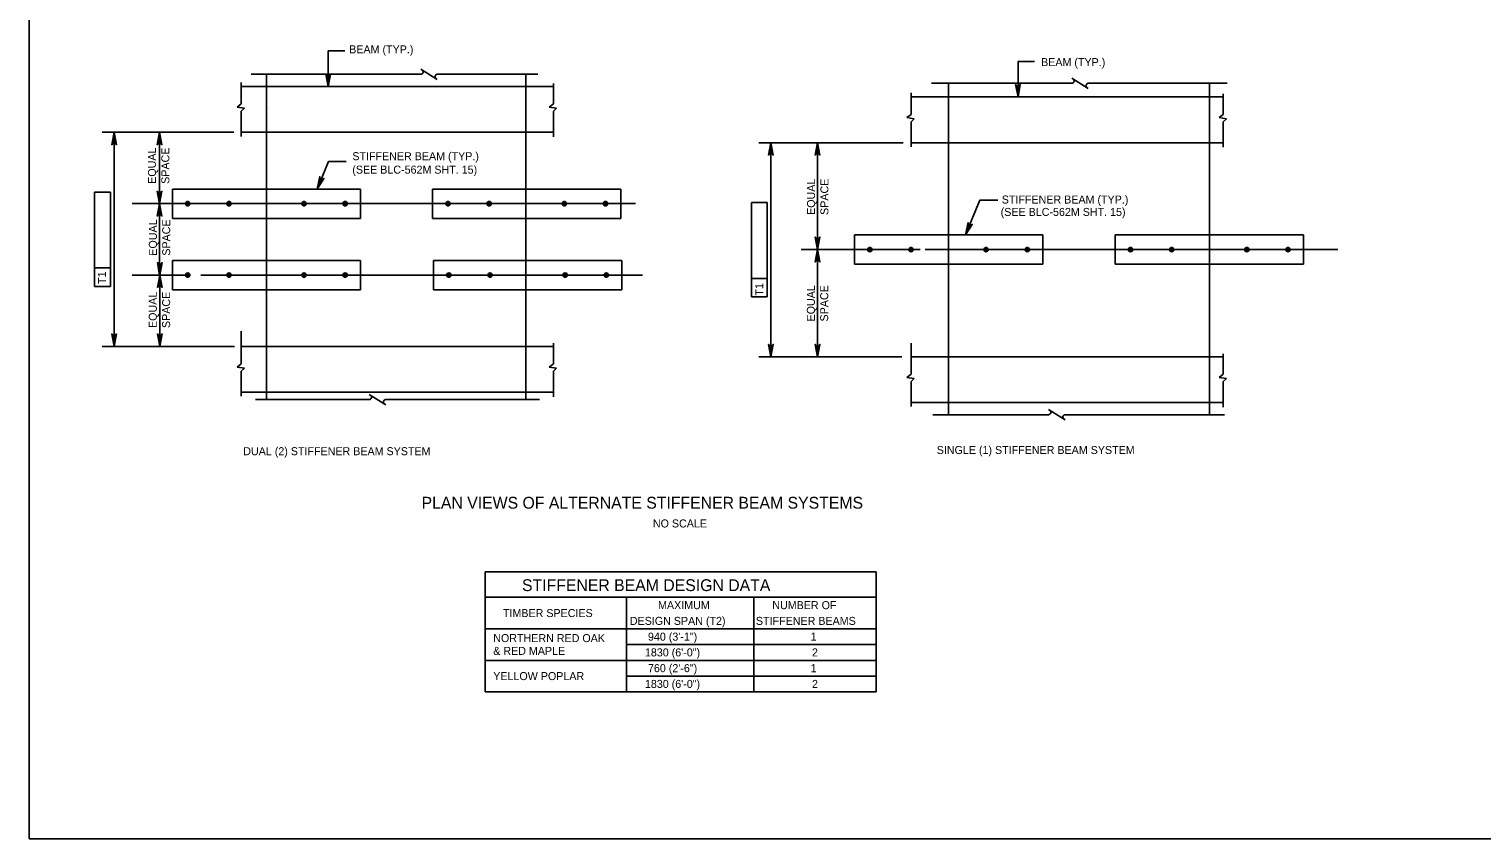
# Model space of a CAD drawing. Extents: x 638263 to 640360, y 293683 to 298655.
# Drawn here: x 639316 to 639861, y 295480 to 295784 of the extents above; entities that cross this region are included whole.
import ezdxf

# ---------------------------------------------------------------- set-up
doc = ezdxf.new("R2010")
doc.units = 0
for name, color, linetype in [('10', 7, 'Continuous'), ('2', 7, 'Continuous'), ('3', 7, 'Continuous'), ('4', 7, 'Continuous'), ('8', 7, 'Continuous')]:
    doc.layers.add(name, color=color, linetype=linetype)

msp = doc.modelspace()

# ---------------------------------------------------------------- linework, layer by layer
at = {"layer": '10'}
for p, q in [((639487.48, 295580.54), (639487.48, 295535.57)), ((639487.48, 295580.54), (639634.13, 295580.54)), ((639634.13, 295580.54), (639634.13, 295535.57)), ((639487.48, 295571), (639634.13, 295571)), ((639540.46, 295571), (639540.46, 295535.57)), ((639588.23, 295571), (639588.23, 295535.57)), ((639487.48, 295559.19), (639634.13, 295559.19)), ((639540.46, 295553.28), (639634.13, 295553.28)), ((639487.48, 295547.38), (639634.13, 295547.38)), ((639540.46, 295541.47), (639634.13, 295541.47)), ((639487.48, 295535.57), (639634.13, 295535.57))]:
    msp.add_line(p, q, dxfattribs=at)
at = {"layer": '2'}
for p, q in [((639316.46, 295480.46), (639316.46, 296044.46)), ((639405.49, 295645.1), (639405.49, 295767.05)), ((639502.74, 295645.1), (639502.74, 295767.05)), ((639661.25, 295639.44), (639661.25, 295763.63)), ((639759.08, 295639.44), (639759.08, 295763.63)), ((640102.46, 295480.46), (639316.46, 295480.46))]:
    msp.add_line(p, q, dxfattribs=at)
at = {"layer": '3'}
for p, q in [((639399.75, 295767.05), (639463.3, 295767.05)), ((639463.37, 295768.98), (639469.53, 295765.11)), ((639469.51, 295767.05), (639507.21, 295767.05)), ((639707.48, 295765.57), (639713.64, 295761.7)), ((639395.99, 295755.88), (639395.99, 295763.98)), ((639395.99, 295762.42), (639513.06, 295762.42)), ((639513.06, 295755.88), (639513.06, 295763.61)), ((639647.19, 295751.96), (639647.19, 295760.06)), ((639654.87, 295763.63), (639707.41, 295763.63)), ((639713.63, 295763.63), (639765.7, 295763.63)), ((639394.45, 295754.69), (639395.99, 295755.88)), ((639397.21, 295754.27), (639394.45, 295754.69)), ((639511.52, 295754.69), (639513.06, 295755.88)), ((639514.28, 295754.27), (639511.52, 295754.69)), ((639647.19, 295758.5), (639764.26, 295758.5)), ((639764.26, 295751.96), (639764.26, 295759.68)), ((639395.99, 295753.17), (639397.21, 295754.27)), ((639395.99, 295743.75), (639395.99, 295753.17)), ((639513.06, 295753.17), (639514.28, 295754.27)), ((639513.06, 295743.56), (639513.06, 295753.17)), ((639645.65, 295750.77), (639647.19, 295751.96)), ((639648.4, 295750.34), (639645.65, 295750.77)), ((639647.19, 295749.25), (639648.4, 295750.34)), ((639647.19, 295739.83), (639647.19, 295749.25)), ((639762.72, 295750.77), (639764.26, 295751.96)), ((639765.48, 295750.34), (639762.72, 295750.77)), ((639764.26, 295749.25), (639765.48, 295750.34)), ((639764.26, 295739.64), (639764.26, 295749.25)), ((639513.06, 295745.29), (639395.99, 295745.29)), ((639764.26, 295741.37), (639647.19, 295741.37)), ((639370.2, 295724.02), (639370.2, 295713)), ((639370.2, 295724.02), (639440.77, 295724.02)), ((639440.77, 295724.02), (639440.77, 295713)), ((639467.79, 295724.02), (639467.79, 295713)), ((639467.79, 295724.02), (639538.36, 295724.02)), ((639538.36, 295724.02), (639538.36, 295713)), ((639405.4, 295718.54), (639405.4, 295718.54)), ((639370.2, 295713), (639440.77, 295713)), ((639467.79, 295713), (639538.36, 295713)), ((639625.96, 295706.82), (639696.54, 295706.82)), ((639625.96, 295706.82), (639625.96, 295695.8)), ((639696.54, 295706.82), (639696.54, 295695.8)), ((639723.71, 295706.82), (639723.71, 295695.8)), ((639723.71, 295706.82), (639794.28, 295706.82)), ((639794.28, 295706.82), (639794.28, 295695.8)), ((639370.2, 295697.27), (639440.77, 295697.27)), ((639370.2, 295697.27), (639370.2, 295686.25)), ((639440.77, 295697.27), (639440.77, 295686.25)), ((639468.12, 295697.27), (639538.69, 295697.27)), ((639468.12, 295697.27), (639468.12, 295686.25)), ((639538.69, 295697.27), (639538.69, 295686.25)), ((639625.96, 295695.8), (639696.54, 295695.8)), ((639723.71, 295695.8), (639794.28, 295695.8)), ((639405.4, 295691.79), (639405.4, 295691.79)), ((639370.2, 295686.25), (639440.77, 295686.25)), ((639468.12, 295686.25), (639538.69, 295686.25)), ((639395.99, 295658.5), (639395.99, 295670.77)), ((639395.99, 295658.5), (639395.99, 295666.6)), ((639395.99, 295665.04), (639513.06, 295665.04)), ((639513.06, 295658.5), (639513.06, 295666.22)), ((639647.19, 295658.24), (639647.19, 295666.19)), ((639647.19, 295654.58), (639647.19, 295662.68)), ((639764.26, 295654.58), (639764.26, 295662.3)), ((639394.45, 295657.31), (639395.99, 295658.5)), ((639397.21, 295656.89), (639394.45, 295657.31)), ((639395.99, 295655.79), (639397.21, 295656.89)), ((639511.52, 295657.31), (639513.06, 295658.5)), ((639514.28, 295656.89), (639511.52, 295657.31)), ((639513.06, 295655.79), (639514.28, 295656.89)), ((639647.19, 295661.12), (639764.26, 295661.12)), ((639395.99, 295646.37), (639395.99, 295655.79)), ((639513.06, 295646.18), (639513.06, 295655.79)), ((639645.65, 295653.39), (639647.19, 295654.58)), ((639648.41, 295652.97), (639645.65, 295653.39)), ((639647.19, 295651.87), (639648.41, 295652.97)), ((639647.19, 295642.45), (639647.19, 295651.87)), ((639762.72, 295653.39), (639764.26, 295654.58)), ((639765.48, 295652.97), (639762.72, 295653.39)), ((639764.26, 295651.87), (639765.48, 295652.97)), ((639764.26, 295642.26), (639764.26, 295651.87)), ((639513.06, 295647.91), (639395.99, 295647.91)), ((639444.02, 295647.03), (639450.18, 295643.16)), ((639401.4, 295645.1), (639443.95, 295645.1)), ((639450.17, 295645.1), (639507.87, 295645.1)), ((639764.26, 295643.99), (639647.19, 295643.99)), ((639698.78, 295641.38), (639704.94, 295637.51)), ((639655.3, 295639.44), (639698.71, 295639.44)), ((639704.93, 295639.44), (639764.73, 295639.44))]:
    msp.add_line(p, q, dxfattribs=at)
for centre, radius in [((639375.96, 295718.51), 0.833), ((639375.96, 295718.51), 0.738), ((639375.96, 295718.51), 0.625), ((639375.96, 295718.51), 0.417), ((639375.96, 295718.51), 0.208), ((639391.41, 295718.51), 0.833), ((639391.41, 295718.51), 0.738), ((639391.41, 295718.51), 0.625), ((639391.41, 295718.51), 0.417), ((639391.41, 295718.51), 0.208), ((639419.56, 295718.51), 0.833), ((639419.56, 295718.51), 0.738), ((639419.56, 295718.51), 0.625), ((639419.56, 295718.51), 0.417), ((639419.56, 295718.51), 0.208), ((639435.01, 295718.51), 0.833), ((639435.01, 295718.51), 0.738), ((639435.01, 295718.51), 0.625), ((639435.01, 295718.51), 0.417), ((639435.01, 295718.51), 0.208), ((639473.55, 295718.51), 0.833), ((639473.55, 295718.51), 0.738), ((639473.55, 295718.51), 0.625), ((639473.55, 295718.51), 0.417), ((639473.55, 295718.51), 0.208), ((639489, 295718.51), 0.833), ((639489, 295718.51), 0.738), ((639489, 295718.51), 0.625), ((639489, 295718.51), 0.417), ((639489, 295718.51), 0.208), ((639517.15, 295718.51), 0.833), ((639517.15, 295718.51), 0.738), ((639517.15, 295718.51), 0.625), ((639517.15, 295718.51), 0.417), ((639517.15, 295718.51), 0.208), ((639532.6, 295718.51), 0.833), ((639532.6, 295718.51), 0.738), ((639532.6, 295718.51), 0.625), ((639532.6, 295718.51), 0.417), ((639532.6, 295718.51), 0.208), ((639631.72, 295701.31), 0.833), ((639631.72, 295701.31), 0.738), ((639631.72, 295701.31), 0.625), ((639631.72, 295701.31), 0.417), ((639631.72, 295701.31), 0.208), ((639647.17, 295701.31), 0.833), ((639647.17, 295701.31), 0.738), ((639647.17, 295701.31), 0.625), ((639647.17, 295701.31), 0.417), ((639647.17, 295701.31), 0.208), ((639675.32, 295701.31), 0.833), ((639675.32, 295701.31), 0.738), ((639675.32, 295701.31), 0.625), ((639675.32, 295701.31), 0.417), ((639675.32, 295701.31), 0.208), ((639690.78, 295701.31), 0.833), ((639690.78, 295701.31), 0.738), ((639690.78, 295701.31), 0.625), ((639690.78, 295701.31), 0.417), ((639690.78, 295701.31), 0.208), ((639729.47, 295701.31), 0.833), ((639729.47, 295701.31), 0.738), ((639729.47, 295701.31), 0.625), ((639729.47, 295701.31), 0.417), ((639729.47, 295701.31), 0.208), ((639744.92, 295701.31), 0.833), ((639744.92, 295701.31), 0.738), ((639744.92, 295701.31), 0.625), ((639744.92, 295701.31), 0.417), ((639744.92, 295701.31), 0.208), ((639773.07, 295701.31), 0.833), ((639773.07, 295701.31), 0.738), ((639773.07, 295701.31), 0.625), ((639773.07, 295701.31), 0.417), ((639773.07, 295701.31), 0.208), ((639788.52, 295701.31), 0.833), ((639788.52, 295701.31), 0.738), ((639788.52, 295701.31), 0.625), ((639788.52, 295701.31), 0.417), ((639788.52, 295701.31), 0.208), ((639375.96, 295691.76), 0.833), ((639375.96, 295691.76), 0.738), ((639375.96, 295691.76), 0.625), ((639375.96, 295691.76), 0.417), ((639375.96, 295691.76), 0.208), ((639391.41, 295691.76), 0.833), ((639391.41, 295691.76), 0.738), ((639391.41, 295691.76), 0.625), ((639391.41, 295691.76), 0.417), ((639391.41, 295691.76), 0.208), ((639419.56, 295691.76), 0.833), ((639419.56, 295691.76), 0.738), ((639419.56, 295691.76), 0.625), ((639419.56, 295691.76), 0.417), ((639419.56, 295691.76), 0.208), ((639435.01, 295691.76), 0.833), ((639435.01, 295691.76), 0.738), ((639435.01, 295691.76), 0.625), ((639435.01, 295691.76), 0.417), ((639435.01, 295691.76), 0.208), ((639473.88, 295691.76), 0.833), ((639473.88, 295691.76), 0.738), ((639473.88, 295691.76), 0.625), ((639473.88, 295691.76), 0.417), ((639473.88, 295691.76), 0.208), ((639489.33, 295691.76), 0.833), ((639489.33, 295691.76), 0.738), ((639489.33, 295691.76), 0.625), ((639489.33, 295691.76), 0.417), ((639489.33, 295691.76), 0.208), ((639517.48, 295691.76), 0.833), ((639517.48, 295691.76), 0.738), ((639517.48, 295691.76), 0.625), ((639517.48, 295691.76), 0.417), ((639517.48, 295691.76), 0.208), ((639532.93, 295691.76), 0.833), ((639532.93, 295691.76), 0.738), ((639532.93, 295691.76), 0.625), ((639532.93, 295691.76), 0.417), ((639532.93, 295691.76), 0.208)]:
    msp.add_circle(centre, radius, dxfattribs=at)
for centre, start, end in [((639463.3, 295767.96), 270, 60), ((639469.6, 295766.14), 95.3286, 237.8672), ((639707.41, 295764.54), 270, 60), ((639713.71, 295762.73), 95.3286, 237.8672), ((639443.95, 295646.01), 270, 60), ((639450.25, 295644.19), 95.3286, 237.8672), ((639698.71, 295640.35), 270, 60), ((639705.01, 295638.54), 95.3286, 237.8672)]:
    msp.add_arc(centre, 0.909, start, end, dxfattribs=at)
at = {"layer": '4'}
for p, q in [((639428.57, 295775.75), (639434.83, 295775.75)), ((639687.28, 295771.83), (639693.5, 295771.83)), ((639393.3, 295745.29), (639343.82, 295745.29)), ((639348.32, 295745.29), (639348.32, 295665.04)), ((639378.25, 295745.29), (639363.19, 295745.29)), ((639365.4, 295745.29), (639365.4, 295718.54)), ((639644.24, 295741.37), (639590.11, 295741.37)), ((639594.61, 295741.37), (639594.61, 295661.12)), ((639612.12, 295741.37), (639612.12, 295701.34)), ((639428.75, 295734.33), (639435.41, 295734.33)), ((639341.04, 295722.84), (639346.94, 295722.84)), ((639341.04, 295687.54), (639341.04, 295722.84)), ((639346.94, 295722.84), (639346.94, 295687.54)), ((639355.11, 295718.54), (639391.41, 295718.54)), ((639363.55, 295718.54), (639543.8, 295718.54)), ((639365.4, 295718.54), (639365.4, 295694.74)), ((639587.32, 295718.92), (639593.23, 295718.92)), ((639587.32, 295691.09), (639587.32, 295718.92)), ((639593.23, 295718.92), (639593.23, 295683.62)), ((639672.99, 295719.79), (639679.68, 295719.79)), ((639606, 295701.34), (639650.55, 295701.34)), ((639649.66, 295701.34), (639607.62, 295701.34)), ((639612.12, 295701.34), (639612.12, 295661.12)), ((639652.5, 295701.31), (639807.19, 295701.31)), ((639346.94, 295694.43), (639341.04, 295694.43)), ((639355.11, 295691.79), (639376.9, 295691.79)), ((639380.87, 295691.76), (639546.43, 295691.76)), ((639587.32, 295683.62), (639587.32, 295691.09)), ((639593.23, 295690.51), (639587.32, 295690.51)), ((639346.94, 295687.54), (639341.04, 295687.54)), ((639365.47, 295688.83), (639365.47, 295665.04)), ((639593.23, 295683.62), (639587.32, 295683.62)), ((639393.52, 295665.04), (639343.82, 295665.04)), ((639371.95, 295665.04), (639363.57, 295665.04)), ((639643.78, 295661.12), (639590.11, 295661.12))]:
    msp.add_line(p, q, dxfattribs=at)
for points in [[(639428.57, 295762.42), (639428.57, 295775.75)], [(639687.29, 295758.5), (639687.29, 295771.83)], [(639428.57, 295762.42), (639427.7, 295767.08), (639427.95, 295766.72), (639428.26, 295766.53), (639428.57, 295766.48), (639428.89, 295766.53), (639429.2, 295766.72), (639429.45, 295767.08), (639428.57, 295762.42), (639429.2, 295766.72), (639428.89, 295766.53), (639428.57, 295762.42), (639428.57, 295766.48), (639428.26, 295766.53), (639428.57, 295762.42), (639427.95, 295766.72)], [(639687.29, 295758.5), (639686.41, 295763.16), (639686.66, 295762.8), (639686.97, 295762.61), (639687.29, 295762.56), (639687.6, 295762.61), (639687.91, 295762.8), (639688.16, 295763.16), (639687.29, 295758.5), (639687.91, 295762.8), (639687.6, 295762.61), (639687.29, 295758.5), (639687.29, 295762.56), (639686.97, 295762.61), (639687.29, 295758.5), (639686.66, 295762.8)], [(639348.32, 295745.29), (639349.2, 295740.63), (639348.95, 295740.99), (639348.64, 295741.18), (639348.32, 295741.23), (639348.01, 295741.18), (639347.7, 295740.99), (639347.45, 295740.63), (639348.32, 295745.29), (639347.7, 295740.99), (639348.01, 295741.18), (639348.32, 295745.29), (639348.32, 295741.23), (639348.64, 295741.18), (639348.32, 295745.29), (639348.95, 295740.99)], [(639365.4, 295745.29), (639366.28, 295740.63), (639366.03, 295740.99), (639365.72, 295741.18), (639365.4, 295741.23), (639365.09, 295741.18), (639364.78, 295740.99), (639364.53, 295740.63), (639365.4, 295745.29), (639364.78, 295740.99), (639365.09, 295741.18), (639365.4, 295745.29), (639365.4, 295741.23), (639365.72, 295741.18), (639365.4, 295745.29), (639366.03, 295740.99)], [(639594.61, 295741.37), (639595.48, 295736.71), (639595.23, 295737.07), (639594.92, 295737.26), (639594.61, 295737.31), (639594.3, 295737.26), (639593.98, 295737.07), (639593.74, 295736.71), (639594.61, 295741.37), (639593.98, 295737.07), (639594.3, 295737.26), (639594.61, 295741.37), (639594.61, 295737.31), (639594.92, 295737.26), (639594.61, 295741.37), (639595.23, 295737.07)], [(639612.12, 295741.37), (639612.99, 295736.71), (639612.74, 295737.07), (639612.43, 295737.26), (639612.12, 295737.31), (639611.8, 295737.26), (639611.49, 295737.07), (639611.24, 295736.71), (639612.12, 295741.37), (639611.49, 295737.07), (639611.8, 295737.26), (639612.12, 295741.37), (639612.12, 295737.31), (639612.43, 295737.26), (639612.12, 295741.37), (639612.74, 295737.07)], [(639424.44, 295724.02), (639428.75, 295734.33)], [(639424.44, 295724.02), (639425.43, 295728.66), (639425.52, 295728.23), (639425.74, 295727.94), (639426.01, 295727.77), (639426.31, 295727.7), (639426.67, 295727.75), (639427.04, 295727.98), (639424.44, 295724.02), (639426.67, 295727.75), (639426.31, 295727.7), (639424.44, 295724.02), (639426.01, 295727.77), (639425.74, 295727.94), (639424.44, 295724.02), (639425.52, 295728.23)], [(639365.4, 295718.54), (639364.53, 295723.2), (639364.78, 295722.84), (639365.09, 295722.66), (639365.4, 295722.6), (639365.72, 295722.66), (639366.03, 295722.84), (639366.28, 295723.2), (639365.4, 295718.54), (639366.03, 295722.84), (639365.72, 295722.66), (639365.4, 295718.54), (639365.4, 295722.6), (639365.09, 295722.66), (639365.4, 295718.54), (639364.78, 295722.84)], [(639365.4, 295718.54), (639364.53, 295713.88), (639364.78, 295714.24), (639365.09, 295714.42), (639365.4, 295714.48), (639365.72, 295714.42), (639366.03, 295714.24), (639366.28, 295713.88), (639365.4, 295718.54), (639366.03, 295714.24), (639365.72, 295714.42), (639365.4, 295718.54), (639365.4, 295714.48), (639365.09, 295714.42), (639365.4, 295718.54), (639364.78, 295714.24)], [(639667.55, 295706.82), (639672.99, 295719.79)], [(639667.55, 295706.82), (639668.55, 295711.46), (639668.64, 295711.03), (639668.86, 295710.74), (639669.13, 295710.57), (639669.43, 295710.5), (639669.79, 295710.55), (639670.16, 295710.78), (639667.55, 295706.82), (639669.79, 295710.55), (639669.43, 295710.5), (639667.55, 295706.82), (639669.13, 295710.57), (639668.86, 295710.74), (639667.55, 295706.82), (639668.64, 295711.03)], [(639612.12, 295701.34), (639612.99, 295706), (639612.74, 295705.64), (639612.43, 295705.46), (639612.12, 295705.4), (639611.8, 295705.46), (639611.49, 295705.64), (639611.24, 295706), (639612.12, 295701.34), (639611.49, 295705.64), (639611.8, 295705.46), (639612.12, 295701.34), (639612.12, 295705.4), (639612.43, 295705.46), (639612.12, 295701.34), (639612.74, 295705.64)], [(639612.12, 295701.34), (639612.99, 295696.68), (639612.74, 295697.04), (639612.43, 295697.22), (639612.12, 295697.28), (639611.8, 295697.22), (639611.49, 295697.04), (639611.24, 295696.68), (639612.12, 295701.34), (639611.49, 295697.04), (639611.8, 295697.22), (639612.12, 295701.34), (639612.12, 295697.28), (639612.43, 295697.22), (639612.12, 295701.34), (639612.74, 295697.04)], [(639365.47, 295691.79), (639364.59, 295696.45), (639364.84, 295696.09), (639365.15, 295695.91), (639365.47, 295695.85), (639365.78, 295695.91), (639366.09, 295696.09), (639366.34, 295696.45), (639365.47, 295691.79), (639366.09, 295696.09), (639365.78, 295695.91), (639365.47, 295691.79), (639365.47, 295695.85), (639365.15, 295695.91), (639365.47, 295691.79), (639364.84, 295696.09)], [(639365.47, 295691.79), (639364.59, 295687.13), (639364.84, 295687.49), (639365.15, 295687.67), (639365.47, 295687.73), (639365.78, 295687.67), (639366.09, 295687.49), (639366.34, 295687.13), (639365.47, 295691.79), (639366.09, 295687.49), (639365.78, 295687.67), (639365.47, 295691.79), (639365.47, 295687.73), (639365.15, 295687.67), (639365.47, 295691.79), (639364.84, 295687.49)], [(639348.32, 295665.04), (639347.45, 295669.7), (639347.7, 295669.34), (639348.01, 295669.15), (639348.32, 295669.1), (639348.64, 295669.15), (639348.95, 295669.34), (639349.2, 295669.7), (639348.32, 295665.04), (639348.95, 295669.34), (639348.64, 295669.15), (639348.32, 295665.04), (639348.32, 295669.1), (639348.01, 295669.15), (639348.32, 295665.04), (639347.7, 295669.34)], [(639365.47, 295665.04), (639364.59, 295669.7), (639364.84, 295669.34), (639365.15, 295669.15), (639365.47, 295669.1), (639365.78, 295669.15), (639366.09, 295669.34), (639366.34, 295669.7), (639365.47, 295665.04), (639366.09, 295669.34), (639365.78, 295669.15), (639365.47, 295665.04), (639365.47, 295669.1), (639365.15, 295669.15), (639365.47, 295665.04), (639364.84, 295669.34)], [(639594.61, 295661.12), (639593.74, 295665.78), (639593.98, 295665.42), (639594.3, 295665.23), (639594.61, 295665.18), (639594.92, 295665.23), (639595.23, 295665.42), (639595.48, 295665.78), (639594.61, 295661.12), (639595.23, 295665.42), (639594.92, 295665.23), (639594.61, 295661.12), (639594.61, 295665.18), (639594.3, 295665.23), (639594.61, 295661.12), (639593.98, 295665.42)], [(639612.12, 295661.12), (639611.24, 295665.78), (639611.49, 295665.42), (639611.8, 295665.23), (639612.12, 295665.18), (639612.43, 295665.23), (639612.74, 295665.42), (639612.99, 295665.78), (639612.12, 295661.12), (639612.74, 295665.42), (639612.43, 295665.23), (639612.12, 295661.12), (639612.12, 295665.18), (639611.8, 295665.23), (639612.12, 295661.12), (639611.49, 295665.42)]]:
    msp.add_lwpolyline(points, dxfattribs=at)
for points in [[(639428.57, 295762.42), (639428.6, 295762.53), (639428.54, 295762.53)], [(639687.29, 295758.5), (639687.31, 295758.61), (639687.25, 295758.61)], [(639594.11, 295738.37), (639595.11, 295738.37), (639594.61, 295741.37)], [(639611.62, 295738.37), (639612.62, 295738.37), (639612.12, 295741.37)], [(639424.44, 295724.02), (639424.51, 295724.12), (639424.45, 295724.14)], [(639667.55, 295706.82), (639667.63, 295706.92), (639667.57, 295706.94)], [(639611.62, 295704.34), (639612.62, 295704.34), (639612.12, 295701.34)], [(639611.62, 295698.34), (639612.62, 295698.34), (639612.12, 295701.34)], [(639364.91, 295694.74), (639365.9, 295694.74), (639365.4, 295691.79)], [(639364.97, 295688.83), (639365.96, 295688.83), (639365.47, 295691.79)], [(639347.82, 295668.04), (639348.82, 295668.04), (639348.32, 295665.04)], [(639364.97, 295667.99), (639365.96, 295667.99), (639365.47, 295665.04)], [(639594.11, 295664.12), (639595.11, 295664.12), (639594.61, 295661.12)], [(639611.62, 295664.31), (639612.62, 295664.31), (639612.12, 295661.31)]]:
    msp.add_lwpolyline(points, close=True, dxfattribs=at)
at = {"layer": '8'}
for p, q in [((639406.27, 295754.52), (639406.27, 295754.52)), ((639406.28, 295754.55), (639406.28, 295754.55)), ((639405.4, 295718.54), (639405.4, 295718.54)), ((639405.4, 295691.79), (639405.4, 295691.79)), ((639405.49, 295657.14), (639405.49, 295657.14))]:
    msp.add_line(p, q, dxfattribs=at)

# ---------------------------------------------------------------- texts
at = {"layer": '4'}
for s, height, p in [('BEAM (TYP.)', 3, (639436.5, 295774.86)), ('BEAM (TYP.)', 3, (639695.94, 295770.07)), ('STIFFENER BEAM (TYP.)', 3, (639437.67, 295734.82)), ('(SEE BLC-562M SHT. 15)', 3, (639437.67, 295729.78)), ('(SEE BLC-562M SHT. 15)', 3, (639680.8, 295713.93)), ('STIFFENER BEAM (TYP.)', 3, (639681.2, 295718.58)), ('DUAL (2) STIFFENER BEAM SYSTEM', 3, (639396.78, 295624.26)), ('SINGLE (1) STIFFENER BEAM SYSTEM', 3, (639656.81, 295624.72)), ('PLAN VIEWS OF ALTERNATE STIFFENER BEAM SYSTEMS', 4.4292, (639463.64, 295604.23)), ('NO SCALE', 3, (639550.38, 295597.18)), ('STIFFENER BEAM DESIGN DATA', 4.4292, (639501.3, 295573.34)), ('MAXIMUM', 3, (639552.31, 295566.57)), ('NUMBER OF ', 3, (639595.15, 295566.57)), ('TIMBER SPECIES', 3, (639494.15, 295563.6)), ('DESIGN SPAN (T2)', 3, (639541.73, 295560.67)), ('STIFFENER BEAMS', 3, (639589.01, 295560.67)), ('NORTHERN RED OAK', 3, (639490.51, 295554.22)), ('940 (3\'-1")', 3, (639548.53, 295554.76)), ('1', 3, (639609.5, 295554.76)), ('& RED MAPLE', 3, (639490.51, 295549.44)), ('1830 (6\'-0")', 3, (639547.39, 295548.86)), ('2', 3, (639610.03, 295548.86)), ('YELLOW POPLAR', 3, (639490.51, 295539.98)), ('760 (2\'-6")', 3, (639548.53, 295542.95)), ('1', 3, (639609.5, 295542.95)), ('1830 (6\'-0")', 3, (639547.39, 295537.05)), ('2', 3, (639610.03, 295537.05))]:
    msp.add_text(s, height=height, dxfattribs=at).set_placement(p)
for p in [(639345.29, 295688.42), (639591.79, 295684.05)]:
    msp.add_text('T1', height=3, rotation=90, dxfattribs=at).set_placement(p)
at = {"layer": '8'}
for s, p in [('EQUAL ', (639364.05, 295725.96)), ('SPACE', (639369.05, 295725.95)), ('EQUAL ', (639611.18, 295714.3)), ('SPACE', (639616.18, 295714.3)), ('EQUAL ', (639364.39, 295699.02)), ('SPACE', (639369.39, 295699.02)), ('EQUAL ', (639364.35, 295671.92)), ('SPACE', (639369.35, 295671.91)), ('EQUAL ', (639611.12, 295674.37)), ('SPACE', (639616.12, 295674.37))]:
    msp.add_text(s, height=3, rotation=89.9708, dxfattribs=at).set_placement(p)

doc.saveas('drawing.dxf')
